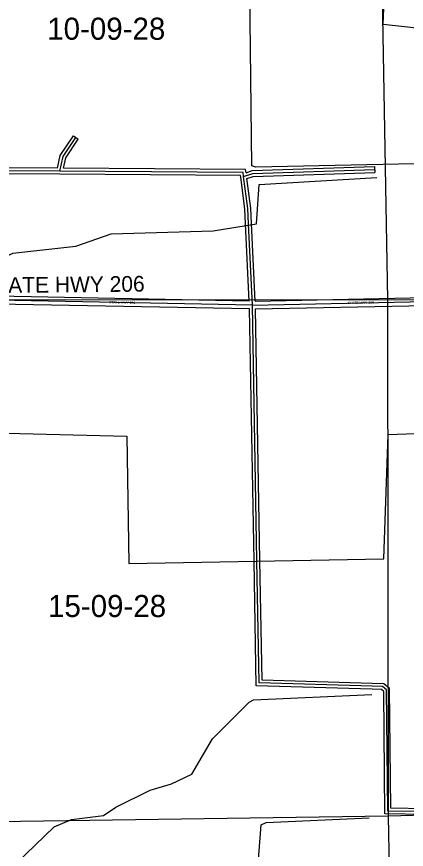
# Model space of a CAD drawing. Extents: x 418523 to 616617, y 1878279 to 2196743.
# Drawn here: x 506917 to 510891, y 1954823 to 1963310 of the extents above; entities that cross this region are included whole.
import ezdxf

# ---------------------------------------------------------------- set-up
doc = ezdxf.new("R2010")
doc.units = 0
for name, color, linetype in [('Level 1', 7, 'Continuous'), ('Level 2', 7, 'Continuous'), ('Level 22', 7, 'Continuous'), ('Level 23', 7, 'Continuous'), ('Level 28', 7, 'Continuous'), ('Level 31', 7, 'Continuous'), ('Level 32', 7, 'Continuous'), ('Level 34', 7, 'Continuous'), ('Level 5', 7, 'Continuous')]:
    doc.layers.add(name, color=color, linetype=linetype)

msp = doc.modelspace()

# ---------------------------------------------------------------- linework, layer by layer
at = {"layer": 'Level 1'}
for p, q in [((510602.689, 1965789.733), (510698.794, 1960423.091)), ((510698.794, 1960423.091), (516007.234, 1960490.524)), ((505319.094, 1960426.358), (510698.794, 1960423.091)), ((510698.794, 1960423.091), (510703.99, 1955161.354)), ((516071, 1955288.293), (510703.99, 1955161.354)), ((510703.99, 1955161.354), (505309.475, 1955082.7)), ((510703.99, 1955161.354), (510823.941, 1949780.482))]:
    msp.add_line(p, q, dxfattribs=at)
at = {"layer": 'Level 22'}
for q in [(506653.519, 1960422.381), (511985.707, 1960426.185)]:
    msp.add_line((509320.988, 1960370.541), q, dxfattribs=at)
at = {"layer": 'Level 23'}
for p, q in [((509289.046, 1960411.169), (506654.296, 1960462.373)), ((509349.115, 1960411.137), (511984.872, 1960466.176)), ((509291.691, 1960331.101), (506682.929, 1960381.801)), ((509351.701, 1960331.172), (511986.542, 1960386.192))]:
    msp.add_line(p, q, dxfattribs=at)
at = {"layer": 'Level 31'}
for p, q in [((507356.214, 1961734.523), (506666.803, 1961739.501)), ((509320.988, 1960370.541), (509282.073, 1961198.748)), ((509367.743, 1957765.467), (509320.988, 1960370.541)), ((510648.667, 1956481.03), (510542.013, 1956484.361)), ((512027.761, 1955191.89), (510702.394, 1955213.469))]:
    msp.add_line(p, q, dxfattribs=at)
for points in [[(507356.214, 1961734.523), (507389.828, 1961883.487), (507520.756, 1962078.606)], [(509231.932, 1961678.978), (509226.071, 1961721.549), (507356.214, 1961734.523)], [(509231.932, 1961678.978), (509324.749, 1961711.701), (510567.282, 1961752.218)], [(509282.073, 1961198.748), (509274.758, 1961354.423), (509231.932, 1961678.978)], [(510542.013, 1956484.361), (509390.078, 1956519.121), (509367.743, 1957765.467)], [(510702.394, 1955213.469), (510690.122, 1956447.409), (510648.667, 1956481.03)]]:
    msp.add_lwpolyline(points, dxfattribs=at)
at = {"layer": 'Level 32'}
for p, q in [((507495.845, 1962095.323), (507545.668, 1962061.89)), ((507355.998, 1961704.522), (506666.586, 1961709.501)), ((507332.269, 1961764.696), (506696.916, 1961769.285)), ((510566.304, 1961782.202), (510568.26, 1961722.233)), ((509289.045, 1960411.169), (509252.105, 1961197.339)), ((509349.115, 1960411.137), (509312.041, 1961200.156)), ((509337.747, 1957764.928), (509291.69, 1960331.101)), ((509397.74, 1957766.005), (509351.701, 1960331.172)), ((510637.624, 1956451.358), (510541.076, 1956454.374)), ((510659.711, 1956510.7), (510542.95, 1956514.346)), ((511999.095, 1955162.351), (510672.686, 1955183.947)), ((512056.429, 1955221.427), (510732.103, 1955242.99))]:
    msp.add_line(p, q, dxfattribs=at)
for points in [[(507332.269, 1961764.696), (507361.795, 1961895.554), (507495.845, 1962095.323)], [(507393.681, 1961764.264), (507417.86, 1961871.421), (507545.668, 1962061.89)], [(509256.638, 1961719.498), (509252.25, 1961751.368), (507393.681, 1961764.264)], [(509256.638, 1961719.498), (509319.141, 1961741.534), (510566.304, 1961782.202)], [(509264.86, 1961658.775), (509330.356, 1961681.866), (510568.26, 1961722.233)], [(509202.189, 1961675.054), (509199.893, 1961691.73), (507356.006, 1961704.523)], [(509252.105, 1961197.34), (509244.85, 1961351.751), (509202.189, 1961675.054)], [(509312.04, 1961200.156), (509304.666, 1961357.094), (509264.859, 1961658.775)], [(510541.108, 1956454.373), (509360.595, 1956489.996), (509337.747, 1957764.93)], [(510542.917, 1956514.348), (509419.561, 1956548.246), (509397.739, 1957766.004)], [(510672.686, 1955183.947), (510660.263, 1956432.998), (510637.625, 1956451.358)], [(510732.103, 1955242.99), (510719.98, 1956461.82), (510659.71, 1956510.7)]]:
    msp.add_lwpolyline(points, dxfattribs=at)
at = {"layer": 'Level 5'}
for p, q in [((511728.88, 1963117.04), (510653.813, 1963228.878)), ((510661.402, 1957785.172), (510707.13, 1959052.162)), ((509460.683, 1955096.354), (510511.196, 1955143.009))]:
    msp.add_line(p, q, dxfattribs=at)
for points in [[(510653.813, 1963228.878), (510662.71, 1963395.572), (510696.28, 1963470.504), (510696.807, 1963628.888), (510655.255, 1963670.698)], [(511699.594, 1961783.318), (510974.396, 1961810.65), (509357.02, 1961774.167), (509315.398, 1961790.967), (509296.105, 1963575.018)], [(509363.52, 1961198.924), (509389.803, 1961599.003), (510590.47, 1961670.171)], [(506677.915, 1960799.069), (506878.307, 1960898.454), (507520.441, 1960971.424), (507879.297, 1961095.321), (508921.47, 1961125.306), (509363.52, 1961198.924)], [(510707.13, 1959052.162), (512007.76, 1959098.001), (511986.478, 1960256.817)], [(506397.3, 1959074.326), (508039.429, 1959035.716), (508060.263, 1957735.156), (510661.402, 1957785.172)], [(509289.537, 1956322.351), (509331.287, 1956347.231), (510540.254, 1956401.699)], [(507927.255, 1955251.347), (508277.97, 1955425.266), (508494.904, 1955491.271), (508703.646, 1955590.646), (508913.195, 1955948.426), (509289.537, 1956322.351)], [(506146.195, 1953564.755), (506330.534, 1953855.934), (506355.903, 1953964.247), (506606.744, 1954205.176), (506816.391, 1954587.997), (507301.405, 1955053.265), (507476.697, 1955127.739), (507801.944, 1955168.374), (507927.255, 1955251.347)], [(509509.478, 1952111.776), (509358.433, 1954413.097), (509410.572, 1955071.503), (509460.683, 1955096.354)]]:
    msp.add_lwpolyline(points, dxfattribs=at)

# ---------------------------------------------------------------- texts
at = {"layer": 'Level 2'}
for s, p in [('10-09-28', (507228.785, 1963074.55)), ('15-09-28', (507237.149, 1957190.423))]:
    msp.add_text(s, height=225, dxfattribs=at).set_placement(p)
at = {"layer": 'Level 28'}
msp.add_text('STATE HWY 206', height=160, rotation=0.5846611, dxfattribs=at).set_placement((506558.75, 1960490.871))
at = {"layer": 'Level 34'}
for rotation, p in [(358.8858861, (507858.53, 1960386.462)), (1.1955083, (510292.724, 1960380.734))]:
    msp.add_text('STATE HWY 206', height=25, rotation=rotation, dxfattribs=at).set_placement(p)

doc.saveas('drawing.dxf')
